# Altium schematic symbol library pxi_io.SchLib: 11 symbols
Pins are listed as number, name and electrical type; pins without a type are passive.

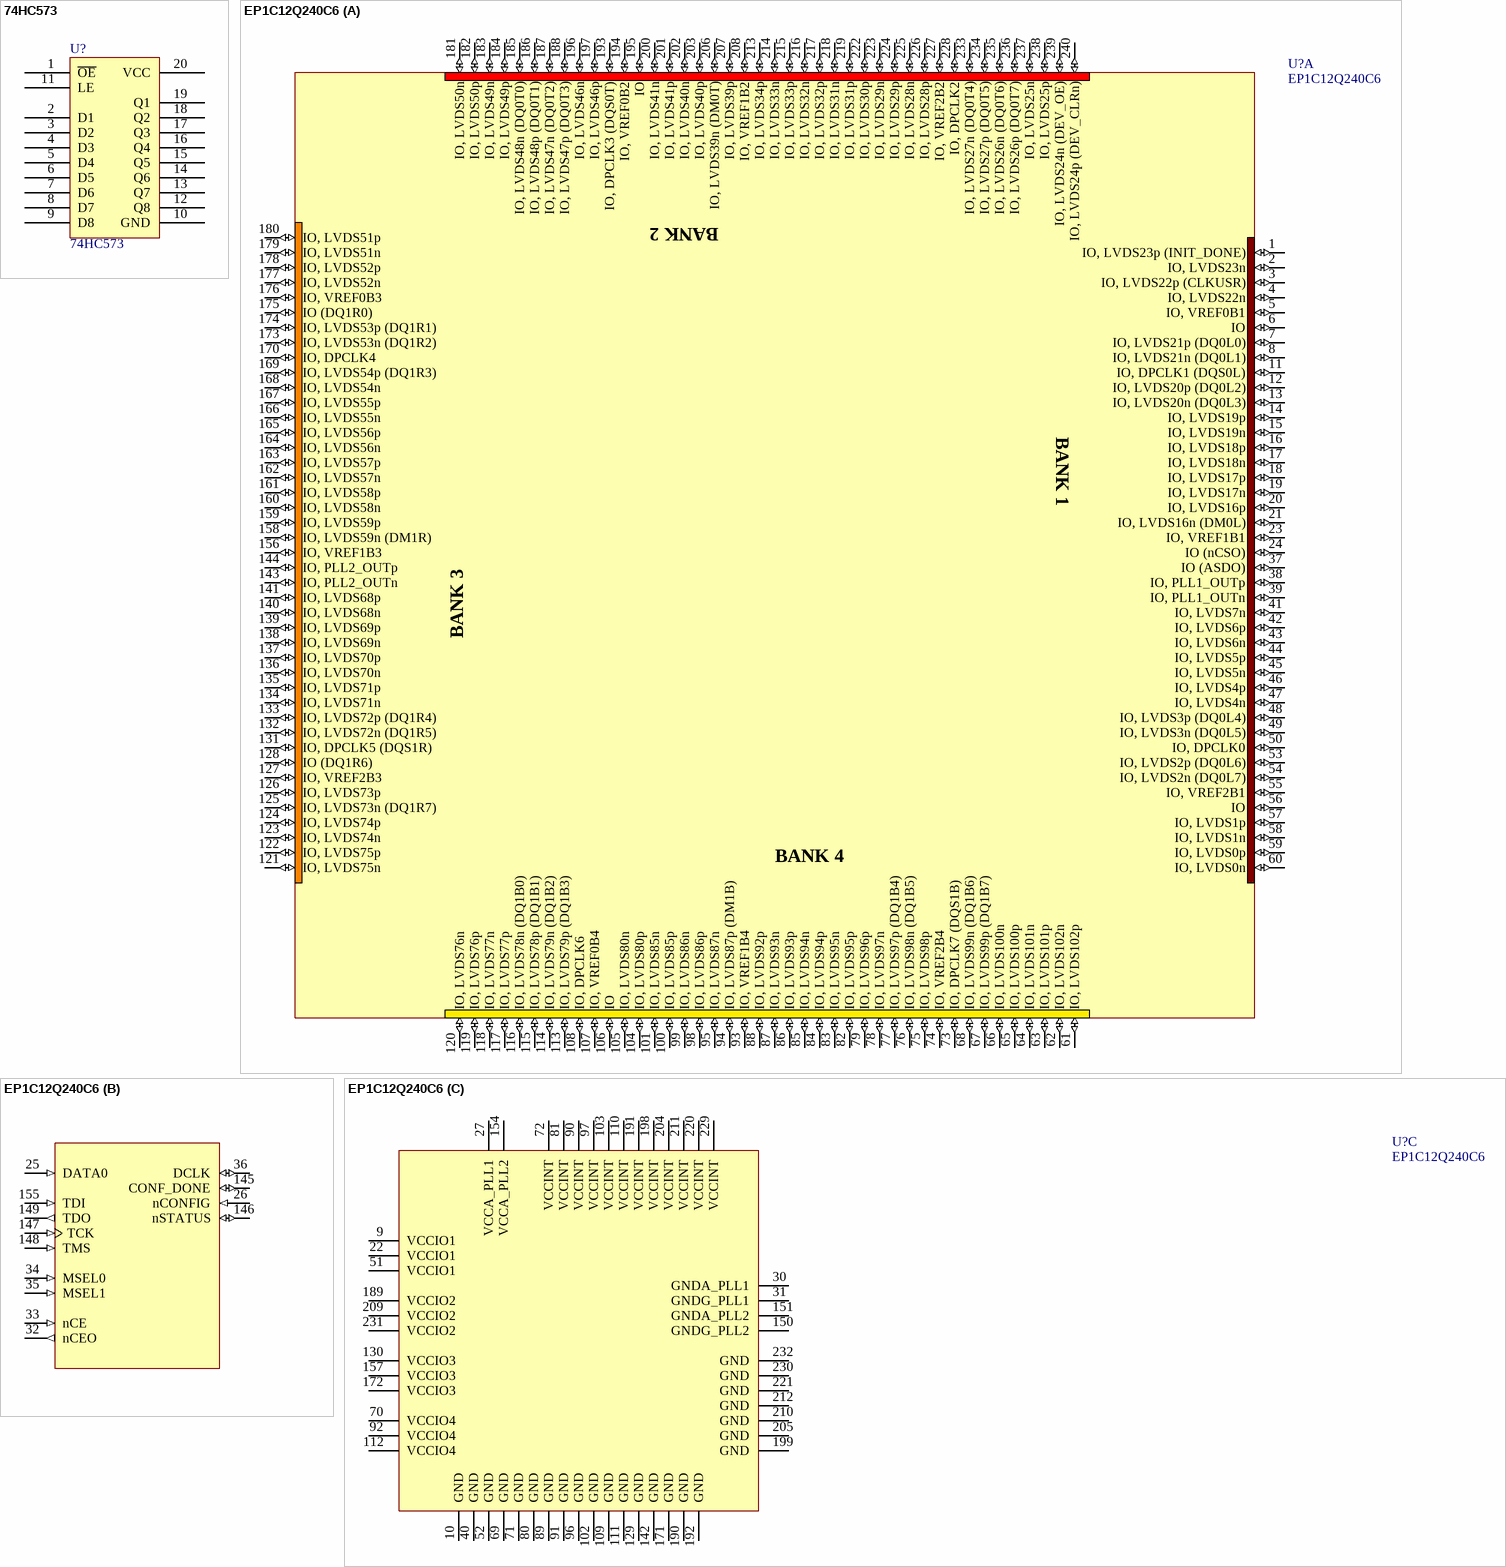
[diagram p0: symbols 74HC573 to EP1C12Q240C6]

## 74HC573
designator U?
footprint SOP20
pins: 1 ~{OE}, 2 D1, 3 D2, 4 D3, 5 D4, 6 D5, 7 D6, 8 D7, 9 D8, 10 GND, 11 LE, 12 Q8, 13 Q7, 14 Q6, 15 Q5, 16 Q4, 17 Q3, 18 Q2, 19 Q1, 20 VCC

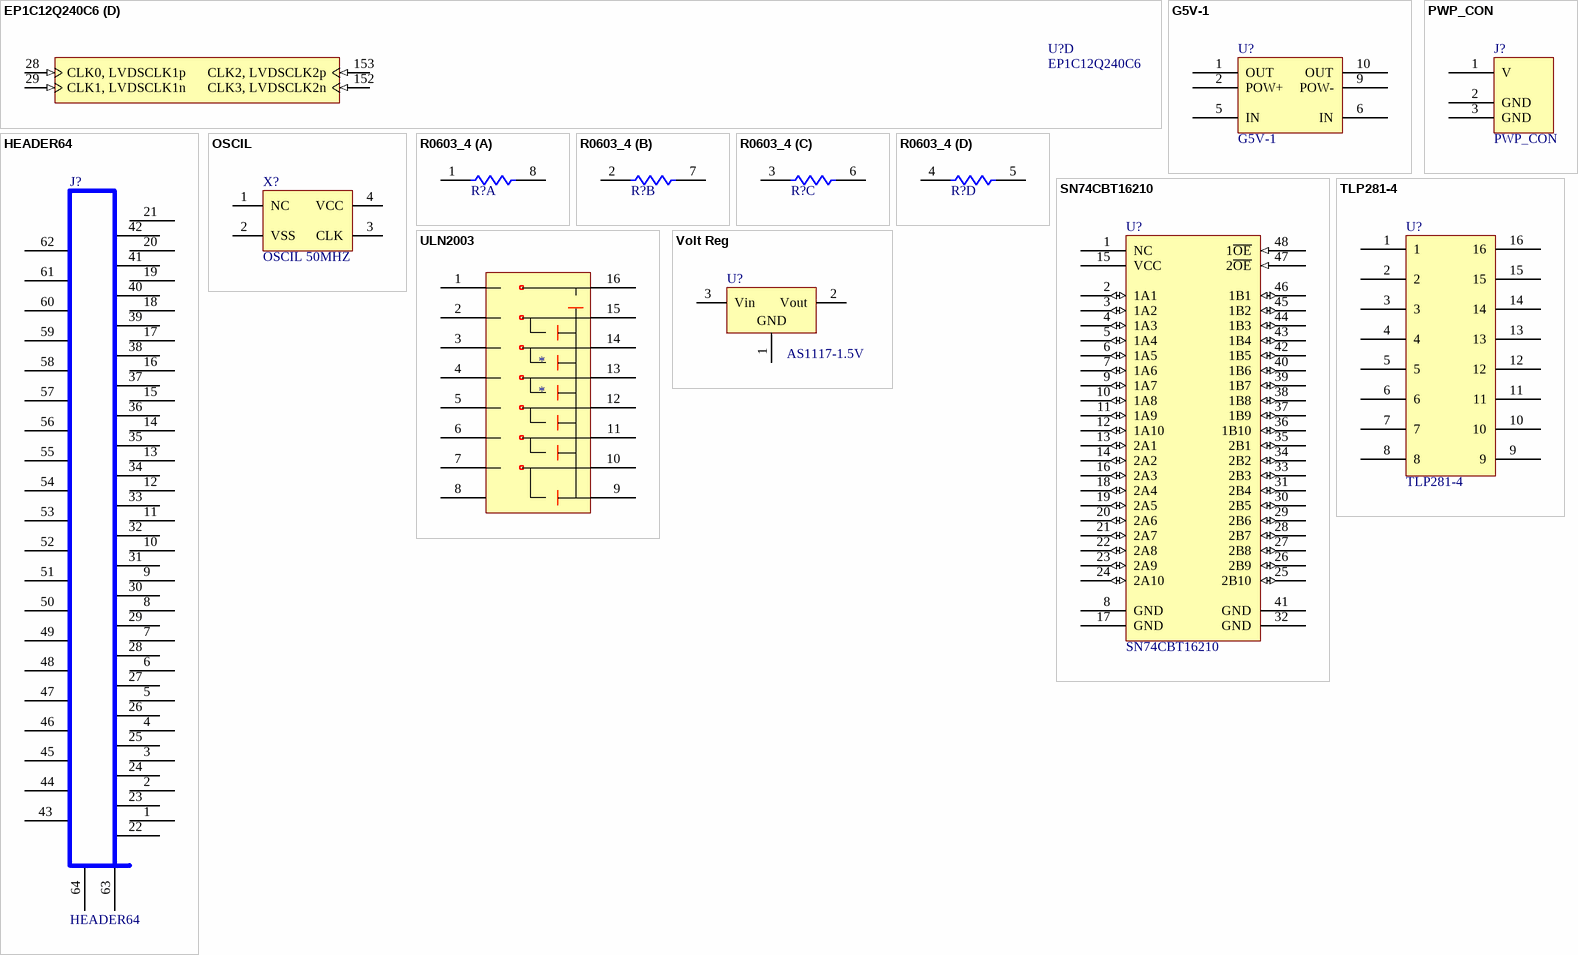
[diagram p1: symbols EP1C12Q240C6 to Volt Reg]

## EP1C12Q240C6
designator U?
Cyclone Family, 1.5V FPGA, 173 I/O Pins, 2 x PLLs, Commercial Grade, Speed Grade 6; Package Information: Latest Revision: ver11.0, Feb-2003; Code - JEDEC: MS-029-GA
footprint PQFP240 (byTX chaned for cyclone FPGA)
3D model EP1C12-PQFP240 (240-Pin Plastic Quad Flat Pack (PQFP))
signal-integrity model 1c (Cyclone)
part A pins: 1 IO, LVDS23p (INIT_DONE) (io), 2 IO, LVDS23n (io), 3 IO, LVDS22p (CLKUSR) (io), 4 IO, LVDS22n (io), 5 IO, VREF0B1 (io), 6 IO (io), 7 IO, LVDS21p (DQ0L0) (io), 8 IO, LVDS21n (DQ0L1) (io), 11 IO, DPCLK1 (DQS0L) (io), 12 IO, LVDS20p (DQ0L2) (io), 13 IO, LVDS20n (DQ0L3) (io), 14 IO, LVDS19p (io), 15 IO, LVDS19n (io), 16 IO, LVDS18p (io), 17 IO, LVDS18n (io), 18 IO, LVDS17p (io), 19 IO, LVDS17n (io), 20 IO, LVDS16p (io), 21 IO, LVDS16n (DM0L) (io), 23 IO, VREF1B1 (io), 24 IO (nCSO) (io), 37 IO (ASDO) (io), 38 IO, PLL1_OUTp (io), 39 IO, PLL1_OUTn (io), 41 IO, LVDS7n (io), 42 IO, LVDS6p (io), 43 IO, LVDS6n (io), 44 IO, LVDS5p (io), 45 IO, LVDS5n (io), 46 IO, LVDS4p (io), 47 IO, LVDS4n (io), 48 IO, LVDS3p (DQ0L4) (io), 49 IO, LVDS3n (DQ0L5) (io), 50 IO, DPCLK0 (io), 53 IO, LVDS2p (DQ0L6) (io), 54 IO, LVDS2n (DQ0L7) (io), 55 IO, VREF2B1 (io), 56 IO (io), 57 IO, LVDS1p (io), 58 IO, LVDS1n (io), 59 IO, LVDS0p (io), 60 IO, LVDS0n (io), 61 IO, LVDS102p (io), 62 IO, LVDS102n (io), 63 IO, LVDS101p (io), 64 IO, LVDS101n (io), 65 IO, LVDS100p (io), 66 IO, LVDS100n (io), 67 IO, LVDS99p (DQ1B7) (io), 68 IO, LVDS99n (DQ1B6) (io), 73 IO, DPCLK7 (DQS1B) (io), 74 IO, VREF2B4 (io), 75 IO, LVDS98p (io), 76 IO, LVDS98n (DQ1B5) (io), 77 IO, LVDS97p (DQ1B4) (io), 78 IO, LVDS97n (io), 79 IO, LVDS96p (io), 82 IO, LVDS95p (io), 83 IO, LVDS95n (io), 84 IO, LVDS94p (io), 85 IO, LVDS94n (io), 86 IO, LVDS93p (io), 87 IO, LVDS93n (io), 88 IO, LVDS92p (io), 93 IO, VREF1B4 (io), 94 IO, LVDS87p (DM1B) (io), 95 IO, LVDS87n (io), 98 IO, LVDS86p (io), 99 IO, LVDS86n (io), 100 IO, LVDS85p (io), 101 IO, LVDS85n (io), 104 IO, LVDS80p (io), 105 IO, LVDS80n (io), 106 IO (io), 107 IO, VREF0B4 (io), 108 IO, DPCLK6 (io), 113 IO, LVDS79p (DQ1B3) (io), 114 IO, LVDS79n (DQ1B2) (io), 115 IO, LVDS78p (DQ1B1) (io), 116 IO, LVDS78n (DQ1B0) (io), 117 IO, LVDS77p (io), 118 IO, LVDS77n (io), 119 IO, LVDS76p (io), 120 IO, LVDS76n (io), 121 IO, LVDS75n (io), 122 IO, LVDS75p (io), 123 IO, LVDS74n (io), 124 IO, LVDS74p (io), 125 IO, LVDS73n (DQ1R7) (io), 126 IO, LVDS73p (io), 127 IO, VREF2B3 (io), 128 IO (DQ1R6) (io), 131 IO, DPCLK5 (DQS1R) (io), 132 IO, LVDS72n (DQ1R5) (io), 133 IO, LVDS72p (DQ1R4) (io), 134 IO, LVDS71n (io), 135 IO, LVDS71p (io), 136 IO, LVDS70n (io), 137 IO, LVDS70p (io), 138 IO, LVDS69n (io), 139 IO, LVDS69p (io), 140 IO, LVDS68n (io), 141 IO, LVDS68p (io), 143 IO, PLL2_OUTn (io), 144 IO, PLL2_OUTp (io), 156 IO, VREF1B3 (io), 158 IO, LVDS59n (DM1R) (io), 159 IO, LVDS59p (io), 160 IO, LVDS58n (io), 161 IO, LVDS58p (io), 162 IO, LVDS57n (io), 163 IO, LVDS57p (io), 164 IO, LVDS56n (io), 165 IO, LVDS56p (io), 166 IO, LVDS55n (io), 167 IO, LVDS55p (io), 168 IO, LVDS54n (io), 169 IO, LVDS54p (DQ1R3) (io), 170 IO, DPCLK4 (io), 173 IO, LVDS53n (DQ1R2) (io), 174 IO, LVDS53p (DQ1R1) (io), 175 IO (DQ1R0) (io), 176 IO, VREF0B3 (io), 177 IO, LVDS52n (io), 178 IO, LVDS52p (io), 179 IO, LVDS51n (io), 180 IO, LVDS51p (io), 181 IO, LVDS50n (io), 182 IO, LVDS50p (io), 183 IO, LVDS49n (io), 184 IO, LVDS49p (io), 185 IO, LVDS48n (DQ0T0) (io), 186 IO, LVDS48p (DQ0T1) (io), 187 IO, LVDS47n (DQ0T2) (io), 188 IO, LVDS47p (DQ0T3) (io), 193 IO, DPCLK3 (DQS0T) (io), 194 IO, VREF0B2 (io), 195 IO (io), 196 IO, LVDS46n (io), 197 IO, LVDS46p (io), 200 IO, LVDS41n (io), 201 IO, LVDS41p (io), 202 IO, LVDS40n (io), 203 IO, LVDS40p (io), 206 IO, LVDS39n (DM0T) (io), 207 IO, LVDS39p (io), 208 IO, VREF1B2 (io), 213 IO, LVDS34p (io), 214 IO, LVDS33n (io), 215 IO, LVDS33p (io), 216 IO, LVDS32n (io), 217 IO, LVDS32p (io), 218 IO, LVDS31n (io), 219 IO, LVDS31p (io), 222 IO, LVDS30p (io), 223 IO, LVDS29n (io), 224 IO, LVDS29p (io), 225 IO, LVDS28n (io), 226 IO, LVDS28p (io), 227 IO, VREF2B2 (io), 228 IO, DPCLK2 (io), 233 IO, LVDS27n (DQ0T4) (io), 234 IO, LVDS27p (DQ0T5) (io), 235 IO, LVDS26n (DQ0T6) (io), 236 IO, LVDS26p (DQ0T7) (io), 237 IO, LVDS25n (io), 238 IO, LVDS25p (io), 239 IO, LVDS24n (DEV_OE) (io), 240 IO, LVDS24p (DEV_CLRn) (io)
part B pins: 25 DATA0 (in), 26 nCONFIG (in), 32 nCEO (out), 33 nCE (in), 34 MSEL0 (in), 35 MSEL1 (in), 36 DCLK (io), 145 CONF_DONE (io), 146 nSTATUS (io), 147 TCK (in), 148 TMS (in), 149 TDO (out), 155 TDI (in)
part C pins: 9 VCCIO1 (power), 10 GND (power), 22 VCCIO1 (power), 27 VCCA_PLL1 (power), 30 GNDA_PLL1 (power), 31 GNDG_PLL1 (power), 40 GND (power), 51 VCCIO1 (power), 52 GND (power), 69 GND (power), 70 VCCIO4 (power), 71 GND (power), 72 VCCINT (power), 80 GND (power), 81 VCCINT (power), 89 GND (power), 90 VCCINT (power), 91 GND (power), 92 VCCIO4 (power), 96 GND (power), 97 VCCINT (power), 102 GND (power), 103 VCCINT (power), 109 GND (power), 110 VCCINT (power), 111 GND (power), 112 VCCIO4 (power), 129 GND (power), 130 VCCIO3 (power), 142 GND (power), 150 GNDG_PLL2 (power), 151 GNDA_PLL2 (power), 154 VCCA_PLL2 (power), 157 VCCIO3 (power), 171 GND (power), 172 VCCIO3 (power), 189 VCCIO2 (power), 190 GND (power), 191 VCCINT (power), 192 GND (power), 198 VCCINT (power), 199 GND (power), 204 VCCINT (power), 205 GND (power), 209 VCCIO2 (power), 210 GND (power), 211 VCCINT (power), 212 GND (power), 220 VCCINT (power), 221 GND (power), 229 VCCINT (power), 230 GND (power), 231 VCCIO2 (power), 232 GND (power)
part D pins: 28 CLK0, LVDSCLK1p (in), 29 CLK1, LVDSCLK1n (in), 152 CLK3, LVDSCLK2n (in), 153 CLK2, LVDSCLK2p (in)

## G5V-1
designator U?
footprint G5V-1-DIP
pins: 1 OUT, 2 POW+, 5 IN, 6 IN, 9 POW-, 10 OUT

## HEADER64
designator J?
footprint HEADER62
pins: 1, 2, 3, 4, 5, 6, 7, 8, 9, 10, 11, 12, 13, 14, 15, 16, 17, 18, 19, 20, 21, 22, 23, 24, 25, 26, 27, 28, 29, 30, 31, 32, 33, 34, 35, 36, 37, 38, 39, 40, 41, 42, 43, 44, 45, 46, 47, 48, 49, 50, 51, 52, 53, 54, 55, 56, 57, 58, 59, 60, 61, 62, 63, 64

## OSCIL
designator X?, comment OSCIL 50MHZ
footprint OSC -BIG
pins: 1 NC, 2 VSS, 3 CLK, 4 VCC

## PWP_CON
designator J?
footprint POWER_CON (Footprint not found)
pins: 1 V (power), 2 GND (power), 3 GND (power)

## R0603_4
designator R?  (value not drawn)
Resistor Array - Parts; Code - JEDEC: MS-012-AC; Code - IPC: SO16; Value: 33
footprint R0603_4 (for ResPackX4____OK!)
part A pins: 1, 8
part B pins: 2, 7
part C pins: 3, 6
part D pins: 4, 5

## SN74CBT16210
designator U?
footprint DGG48
footprint SSOP48 (for CBTD16210)
pins: 1 NC, 2 1A1 (io), 3 1A2 (io), 4 1A3 (io), 5 1A4 (io), 6 1A5 (io), 7 1A6 (io), 8 GND, 9 1A7 (io), 10 1A8 (io), 11 1A9 (io), 12 1A10 (io), 13 2A1 (io), 14 2A2 (io), 15 VCC, 16 2A3 (io), 17 GND, 18 2A4 (io), 19 2A5 (io), 20 2A6 (io), 21 2A7 (io), 22 2A8 (io), 23 2A9 (io), 24 2A10 (io), 25 2B10 (io), 26 2B9 (io), 27 2B8 (io), 28 2B7 (io), 29 2B6 (io), 30 2B5 (io), 31 2B4 (io), 32 GND, 33 2B3 (io), 34 2B2 (io), 35 2B1 (io), 36 1B10 (io), 37 1B9 (io), 38 1B8 (io), 39 1B7 (io), 40 1B6 (io), 41 GND, 42 1B5 (io), 43 1B4 (io), 44 1B3 (io), 45 1B2 (io), 46 1B1 (io), 47 2~{OE} (in), 48 1~{OE} (in)

## TLP281-4
designator U?
footprint TLP281-4
pins: 1, 2, 3, 4, 5, 6, 7, 8, 9, 10, 11, 12, 13, 14, 15, 16

## ULN2003
designator *
footprint ULN2003A
footprint ULN2003L
pins: 1, 2, 3, 4, 5, 6, 7, 8, 9, 10, 11, 12, 13, 14, 15, 16

## Volt Reg
designator U?, comment AS1117-1.5V
Voltage Regulator; Code - JEDEC: SMD-220
footprint LM1117
pins: 1 GND, 2 Vout, 3 Vin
